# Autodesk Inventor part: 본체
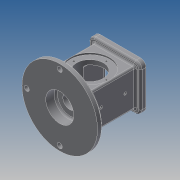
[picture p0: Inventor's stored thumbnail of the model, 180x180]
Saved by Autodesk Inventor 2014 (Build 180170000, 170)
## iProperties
Created: 2019-08
Part Number: 본체
Material: Generic
Document SubType Name: Modeling
Designer: kb542-16
Density: 1 g/cm^3
Appearance: Default
Author: kb542-16
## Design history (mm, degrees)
sketch "스케치1"
  geometry: L1 (37, -33)-(-37, -33); L2 (-37, -33)-(-37, 33); L3 (-37, 33)-(37, 33); L4 (37, 33)-(37, -33); L5 (37, -33)-(-37, 33); L6 (-37, -33)-(37, 33); 1 further point
  constraints: 12 end point, 2 midpoint, 2 parallel, 1 horizontal, 1 perpendicular
  dimensions: "d0" = 66 distance of L1.end L2.end; "d1" = 74 distance of L2.end L3.end
extrude "돌출1" new body sketch "스케치1" distance "d2" = 88; taper "d3" = 0 deg
sketch "스케치2"
  geometry: L1 (46, -41)-(-46, -41); L2 (-46, -41)-(-46, 41); L3 (-46, 41)-(46, 41); L4 (46, 41)-(46, -41); L5 (46, -41)-(-46, 41); L6 (-46, -41)-(46, 41); 1 further point
  constraints: 12 end point, 2 midpoint, 2 parallel, 1 horizontal, 1 perpendicular
  dimensions: "d4" = 92 distance of L2.end L3.end; "d5" = 82 distance of L3.end L1.start
extrude "돌출2" join sketch "스케치2" distance "d6" = 10; taper "d7" = 0 deg
sketch "스케치3"
  geometry: C1 r 67.5 at (0, 0); 1 further point
  constraints: 1 centre point, 1 coincident
  dimensions: "d8" = 135 diameter of C1
extrude "돌출3" join sketch "스케치3" distance "d9" = 10; taper "d10" = 0 deg
sketch "스케치4"
  geometry: C1 r 67.5 at (0, 0) reference; C2 r 25 at (0, 0)
  constraints: 1 centre point, 1 coincident
  dimensions: "d11" = 50 diameter of C2
extrude "돌출4" cut sketch "스케치4" distance "d12" = 18; taper "d13" = 0 deg
sketch "스케치5"
  geometry: C1 r 25 at (0, 0) reference; C2 r 12.5 at (0, 0)
  constraints: 1 centre point, 1 coincident
  dimensions: "d14" = 25 diameter of C2
extrude "돌출5" cut sketch "스케치5" stored distance "d15" = 18; taper "d16" = 0 deg
sketch "스케치6"
  geometry: L1 (74, -88)-(0, -88) reference; L2 (-30.5, -98)-(104.5, -98) reference; C1 r 35 at (37, -44); 2 further points
  constraints: 1 centre point, 1 midpoint, 1 vertical alignment
  dimensions: "d17" = 70 diameter of C1; "d18" = 54 distance from line of L2 C1.centre
extrude "돌출6" cut sketch "스케치6" distance "d19" = 3; taper "d20" = 0 deg
sketch "스케치7"
  geometry: C1 r 35 at (0, 0) reference; C2 r 24 at (0, 0); 1 further point
  constraints: 1 centre point, 1 coincident
  dimensions: "d21" = 48 diameter of C2
extrude "돌출7" cut sketch "스케치7" stored distance "d22" = 3; taper "d23" = 0 deg
sketch "스케치8"
  geometry: L1 (-26, -26)-(26, -26); L2 (26, -26)-(26, 26); L3 (26, 26)-(-26, 26); L4 (-26, 26)-(-26, -26); L5 (-26, -26)-(26, 26); L6 (26, -26)-(-26, 26); C1 r 12.5 at (0, 0) reference
  constraints: 12 end point, 2 midpoint, 2 parallel, 1 horizontal, 1 perpendicular
  dimensions: "d24" = 52 distance of L2.end L3.end; "d25" = 52 distance of L3.end L1.start
extrude "돌출8" cut sketch "스케치8" distance "d26" = 8; taper "d27" = 0 deg
sketch "스케치10"
  geometry: L1 (-22, -22)-(22, -22); L2 (22, -22)-(22, 22); L3 (22, 22)-(-22, 22); L4 (-22, 22)-(-22, -22); L5 (-22, -22)-(22, 22); L6 (22, -22)-(-22, 22); C1 r 12.5 at (0, 0) reference
  constraints: 12 end point, 2 midpoint, 2 parallel, 1 horizontal, 1 perpendicular
  dimensions: "d32" = 44 distance of L3.end L2.end; "d33" = 44 distance of L3.end L1.start
extrude "돌출10" cut sketch "스케치10" distance "d34" = 74; taper "d35" = 0 deg
sketch "스케치11"
  geometry: C1 r 24 at (0, 0) reference; 2 further points
  constraints: 1 vertical alignment
  dimensions: "d36" = 29 distance of C1.centre point (0, 29)
hole "구멍1" sketch "스케치11" at (0, 29) diameter "d37" = 3.242; stored, may be unused: countersink angle "d41" = 90 deg, drill point angle "d43" = 118 deg; dims "d38" = 4, "d39" = 4, "d40" = 2, "d42" = 6
sketch "스케치13"
  geometry: 5 further points
  constraints: 1 horizontal alignment, 1 vertical alignment
  dimensions: "d56" = 72 distance of point (36, 31) point (-36, 31); "d57" = 62 distance of point (-36, 31) point (-36, -31); "d58" = 72 distance of point (36, -31) point (-36, -31); "d59" = 62 distance of point (36, 31) point (36, -31); "d61" = 31 vertical distance of point (0, 0) point (-36, -31); "d62" = 36 horizontal distance of point (0, 0) point (-36, -31)
hole "구멍3" sketch "스케치13" at (-36, 31), (36, 31), (36, -31), (-36, -31) diameter "d63" = 3.242; stored, may be unused: countersink angle "d67" = 90 deg, drill point angle "d69" = 118 deg; dims "d64" = 4, "d65" = 4, "d66" = 2, "d68" = 6
sketch "스케치14" dims "d70" = 118
  geometry: C1 r 67.5 at (0, 0) reference; C2 r 4.5 at (0, 59); 1 further point
  constraints: 2 vertical alignment, 1 centre point, 1 coincident, 2 other
  dimensions: "d71" = 9 diameter of C2
extrude "돌출11" cut sketch "스케치14" stored distance "d72" = 74; taper "d73" = 0 deg
sketch "스케치15"
  geometry: C1 r 67.5 at (0, 0) reference; C2 r 59 at (0, 0)
  constraints: 1 centre point, 1 coincident, 1 other
  dimensions: "d77" = 118 diameter of C2
feature "엠보싱1" sketch "스케치15" dims "d0" = 66, "d1" = 74, "d78" = 0.5, "d79" = 0, "d86" = 1
chamfer "모따기1" distance "d80" = 3; stored, may be unused: second distance "d81" = 2, angle "d82" = 45 deg
fillet "모깎기1" dims "d83" = 10
fillet "모깎기2" dims "d84" = 3
fillet "모깎기3" dims "d85" = 3
chamfer "모따기2" distance "d86" = 1; stored, may be unused: second distance "d87" = 2, angle "d88" = 45 deg
sketch "스케치16"
  geometry: L1 (-97.5, -13)-(37.5, -13) reference; L2 (-61, 95)-(1, 95) reference; 4 further points
  constraints: 2 vertical alignment, 1 midpoint
  dimensions: "d89" = 37 distance from line of point (-30, 24) L1; "d90" = 43 distance of point (-30, 67) point (-30, 24)
hole "구멍5" sketch "스케치16" diameter "d98" = 4.917; stored, may be unused: countersink angle "d102" = 90 deg, drill point angle "d104" = 118 deg; dims "d99" = 4, "d100" = 4, "d101" = 2, "d103" = 6
hole "구멍6" sketch "스케치16" diameter "d105" = 4.917; stored, may be unused: countersink angle "d109" = 90 deg, drill point angle "d111" = 118 deg; dims "d106" = 4, "d107" = 4, "d108" = 2, "d110" = 6
fillet "모깎기4" dims "d112" = 3
fillet "모깎기5" dims "d113" = 3
fillet "모깎기6" dims "d114" = 3
node "솔리드1"
pattern_circular "원형 패턴1" dims angle "d45" = 360 deg
mirror "대칭1"
pattern_circular "원형 패턴2" dims angle "d75" = 180 deg
